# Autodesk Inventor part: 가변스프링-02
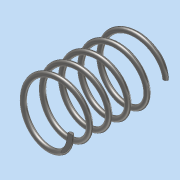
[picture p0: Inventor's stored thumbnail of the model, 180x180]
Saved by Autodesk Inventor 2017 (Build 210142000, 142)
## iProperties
Part Number: 가변스프링-02
Material: 강철, 연강
Document SubType Name: Modeling
Designer: MRC
Mass: 8.42454 g
Surface Area: 21.7273 cm^2
Volume: 1.07319 cm^3
Density: 7.85 g/cm^3
Appearance: 반연마
Author: MRC
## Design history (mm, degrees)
sketch "스케치1"
  geometry: L1 (0, 0)-(0, 37.411); L2 (0, 0)-(11, 0); L3 (0, 37.411)-(11, 37.411); C1 r 1 at (11, 0)
  constraints: 6 end point, 2 horizontal, 1 centre point, 1 coincident, 1 vertical
  dimensions: "d0" = 37.4112 distance of L1.start L1.end (derived); "d1" = 11 distance of L1.start L2.end; "d2" = 2 diameter of C1
feature "코일1" sketch "스케치1" pitch "d3" = 10; turns "d5" = 5; dims "d4" = 37.4112 (= d0), "d6" = 0, angle "d7" = 90 deg, angle "d8" = 90 deg, "d9" = 0, "d10" = 0
sketch "스케치2"
  geometry: L1 (37.411, 15)-(0, 15); L2 (0, 15)-(0, -15); L3 (0, -15)-(37.411, -15); L4 (37.411, -15)-(37.411, 15); 2 further points
  constraints: 8 end point, 2 parallel, 1 coincident, 1 horizontal, 1 midpoint, 1 perpendicular
  dimensions: "d11" = 37.4112 distance of L1.start L1.end (= d0); "d12" = 30 distance of L3.end L1.start
extrude "돌출1" sketch "스케치2" stored distance "d13" = 0; taper "d14" = 0 deg
node "솔리드1"
